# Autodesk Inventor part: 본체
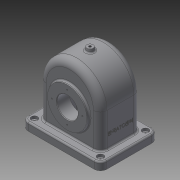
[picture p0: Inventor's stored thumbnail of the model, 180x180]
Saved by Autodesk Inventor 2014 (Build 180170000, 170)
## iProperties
Created: 2016-10
Part Number: 본체
Material: 일반
Document SubType Name: Modeling
Designer: USER
Density: 1 g/cm^3
Appearance: 기본값
Mass: 429.975 g
Surface Area: 1199.61 cm^2
Volume: 429.975 cm^3
Author: USER
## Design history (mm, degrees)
sketch "스케치1"
  geometry: L1 (0, 0)-(58, 0); L2 (58, 0)-(58, 65); L3 (-58, 65)-(-58, 0); L4 (-58, 0)-(0, 0); A1 r 58 centre (0, 65) between (58, 65) and (-58, 65)
  constraints: 8 end point, 2 horizontal, 2 point on circle, 2 tangent, 1 centre point, 1 parallel, 1 perpendicular, 1 vertical alignment
  dimensions: "d0" = 58 radius of A1; "d1" = 65 distance from line of L1 L2.end
extrude "돌출1" new body sketch "스케치1" stored distance "d2" = 77; taper "d3" = 0 deg
sketch "스케치2"
  geometry: L1 (75, 0)-(-75, 0); L2 (-75, 0)-(-75, -15); L3 (-75, -15)-(75, -15); L4 (75, -15)-(75, 0); 2 further points
  constraints: 8 end point, 2 parallel, 1 coincident, 1 horizontal, 1 midpoint, 1 perpendicular
  dimensions: "d4" = 15 distance of L1.end L2.end; "d5" = 150 distance of L2.end L3.end
extrude "돌출2" join sketch "스케치2" stored distance "d6" = 110; taper "d7" = 0 deg
sketch "스케치3"
  geometry: L1 (-75, -15)-(75, -15) reference; C1 r 31 at (0, 50); A1 r 58 centre (0, 65) between (58, 65) and (-58, 65) reference; 1 further point
  constraints: 1 centre point, 1 vertical alignment
  dimensions: "d8" = 62 diameter of C1; "d9" = 65 distance from line of L1 C1.centre
extrude "돌출3" join sketch "스케치3" distance "d10" = 87; taper "d11" = 0 deg
sketch "스케치4"
  geometry: L1 (-75, -15)-(75, -15) reference; C1 r 37.5 at (0, 50); A1 r 58 centre (0, 65) between (58, 65) and (-58, 65) reference; 1 further point
  constraints: 1 centre point, 1 vertical alignment
  dimensions: "d12" = 75 diameter of C1; "d13" = 65 distance from line of L1 C1.centre
extrude "돌출4" join sketch "스케치4" distance "d14" = 5; taper "d15" = 0 deg
sketch "스케치5"
  geometry: L1 (-58, 65)-(-58, 0) reference; L2 (58, 0)-(58, 65) reference; L3 (-52, -15)-(-52, 65); L4 (52, 65)-(52, -15); L5 (-75, -15)-(75, -15) reference; L6 (52, -15)-(-52, -15); A1 r 58 centre (0, 65) between (58, 65) and (-58, 65) reference; A2 r 52 centre (0, 65) between (52, 65) and (-52, 65); 1 further point
  constraints: 6 end point, 2 point on circle, 2 point on line, 1 centre point, 1 collinear
  dimensions: "d16" = 6 radial gap between concentric circles of A1 A2; "d17" = 6 distance between parallel lines of L2 L4; "d18" = 6 distance between parallel lines of L1 L3
extrude "돌출5" cut sketch "스케치5" stored distance "d19" = 67; taper "d20" = 0 deg
sketch "스케치6"
  geometry: L1 (-33.5, 117)-(-33.5, 65) reference; L2 (-33.5, 65)-(-33.5, -15) reference; L3 (-43.5, 87.5)-(-43.5, 12.5) reference; L4 (-33.5, 89.747)-(-19.5, 78); L5 (-19.5, 78)-(-19.5, 50); L6 (-19.5, 50)-(-33.5, 50); L7 (-33.5, 89.747)-(-33.5, 50); 1 further point
  constraints: 8 end point, 2 perpendicular, 2 point on line, 1 horizontal alignment, 1 midpoint, 1 parallel
  dimensions: "d25" = 24 distance between parallel lines of L3 L5; "d26" = 50 deg angle of L4 L5; "d27" = 56 diameter of L4.end L6
revolve "회전1" sketch "스케치6" stored, may be unused: angle "d28" = 90 deg
fillet "모깎기1" dims "d29" = 3
hole "구멍1" diameter "d32" = 40; stored, may be unused: countersink angle "d36" = 90 deg, drill point angle "d38" = 118 deg; dims "d30" = 10, "d31" = 10, "d33" = 6, "d34" = 4, "d35" = 2, "d37" = 8
chamfer "모따기1" distance "d39" = 1; stored, may be unused: second distance "d40" = 2, angle "d41" = 45 deg
sketch "스케치7"
  geometry: L1 (-33.5, 117)-(33.5, 117) reference; L2 (0, 117)-(0, 129); L3 (0, 129)-(6, 129); L4 (6, 129)-(8.116, 117); L5 (8.116, 117)-(0, 117); L6 (-55, -15)-(55, -15) reference; 1 further point
  constraints: 8 end point, 2 perpendicular, 1 collinear, 1 midpoint, 1 point on line
  dimensions: "d42" = 12 vertical distance of L3.end L2; "d43" = 100 deg angle of L1 L4; "d44" = 144 distance between parallel lines of L6 L3
revolve "회전2" sketch "스케치7" stored, may be unused: angle "d45" = 90 deg
fillet "모깎기2" dims "d46" = 3
hole "구멍2" diameter "d49" = 4.459; stored, may be unused: countersink angle "d53" = 90 deg, drill point angle "d55" = 118 deg; dims "d47" = 10, "d48" = 10, "d50" = 6, "d51" = 4, "d52" = 2, "d54" = 8
sketch "스케치8"
  geometry: C1 r 37.5 at (0, 0) reference; 2 further points
  constraints: 1 vertical alignment
  dimensions: "d56" = 29 distance of C1.centre point (0, 29)
hole "구멍3" sketch "스케치8" at (0, 29) diameter "d57" = 2.459; stored, may be unused: countersink angle "d61" = 90 deg, drill point angle "d63" = 118 deg; dims "d58" = 6, "d59" = 4, "d60" = 2, "d62" = 8
sketch "스케치9"
  geometry: C1 r 31 at (0, 0) reference; 2 further points
  constraints: 1 horizontal alignment
  dimensions: "d67" = 26 distance of C1.centre point (-26, 0)
hole "구멍4" sketch "스케치9" at (-26, 0) diameter "d68" = 2.459; stored, may be unused: countersink angle "d72" = 90 deg, drill point angle "d74" = 118 deg; dims "d69" = 6, "d70" = 4, "d71" = 2, "d73" = 8
fillet "모깎기3" dims "d78" = 12
hole "구멍5" diameter "d81" = 5; stored, may be unused: countersink angle "d85" = 90 deg, drill point angle "d87" = 0 deg; dims "d79" = 10, "d80" = 10, "d82" = 6, "d83" = 12, "d84" = 5, "d86" = 8
fillet "모깎기4" dims "d94" = 8
fillet "모깎기5" dims "d95" = 13
fillet "모깎기6" dims "d96" = 3
node "작업 평면1"
sketch "스케치10"
  geometry: L1 (-43, -15)-(43, -15) reference; L2 (-38.5, 65)-(-38.5, 110) reference; 2 further points
  constraints: 1 other
  dimensions: "d98" = 38.5 distance from line of point (0, 25) L2; "d99" = 40 distance from line of L1 point (0, 25)
feature "엠보싱1" sketch "스케치10" dims "d0" = 58, "d1" = 65, "d100" = 0.5, "d101" = 0
node "솔리드1"
pattern_circular "원형 패턴1" dims angle "d65" = 360 deg
pattern_circular "원형 패턴2" dims angle "d76" = 360 deg
pattern_linear "직사각형 패턴1" dims "d90" = 126, "d93" = 86
other parameters: "d97" = 128.5
